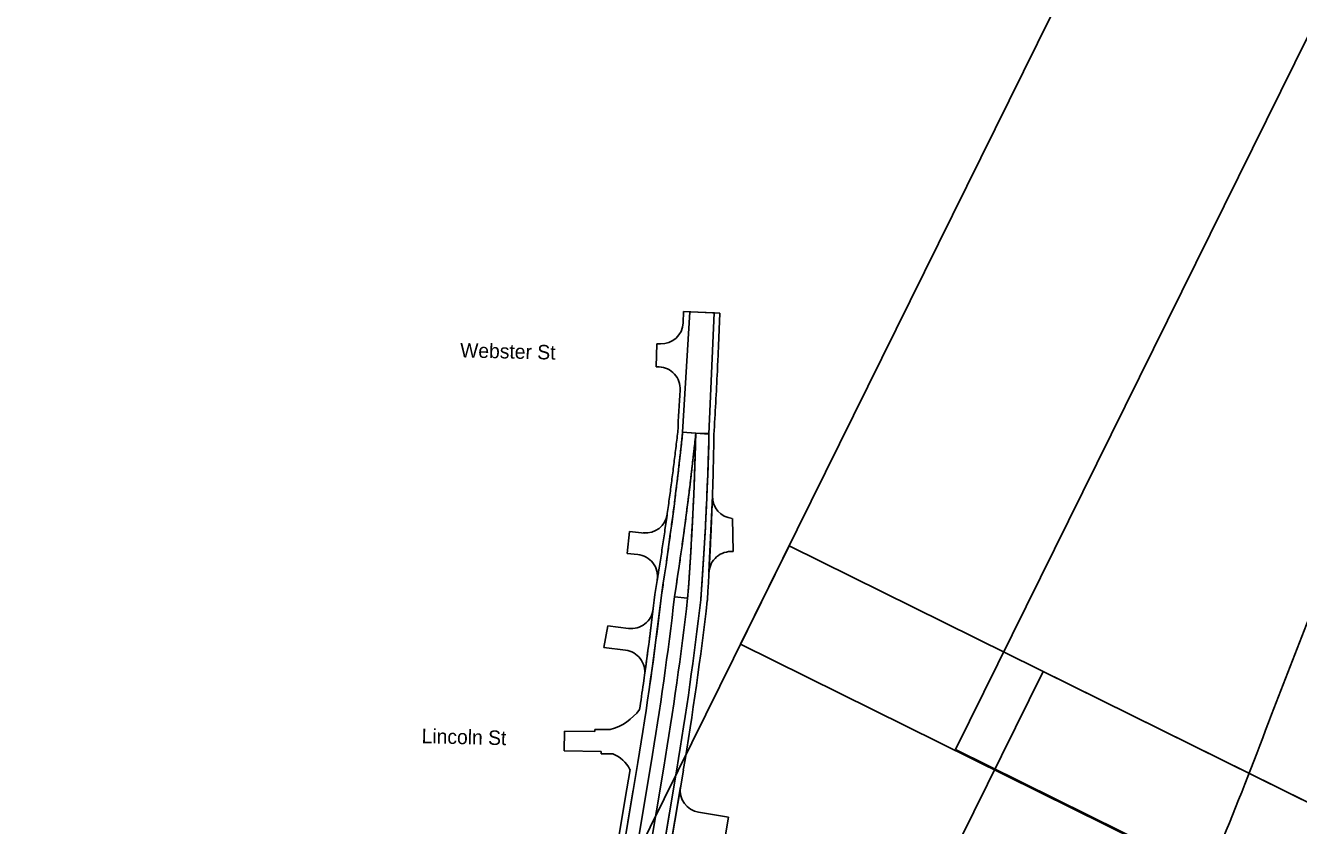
# Model space of a CAD drawing. Extents: x 14097936 to 14128734, y 8632000 to 8683104.
# Drawn here: x 14118632 to 14119790, y 8670096 to 8670823 of the extents above; entities that cross this region are included whole.
import ezdxf

# ---------------------------------------------------------------- set-up
doc = ezdxf.new("R2010")
doc.units = 0
for name, color, linetype in [('dsn_stg_shd_prev', 7, 'Continuous'), ('dsnNonPlotable', 7, 'Continuous'), ('dsnPaintExistingEdgeLineRightWhite', 7, 'Continuous'), ('dsnPaintExistingNoPassingYellow', 7, 'Continuous'), ('dsnPaintPlaceBrokenLaneWhite', 7, 'Continuous'), ('dsnPaintRemoveChannelizingLaneYellow', 7, 'Continuous'), ('dsnShadingPaved', 7, 'Continuous'), ('dsnStdLabel', 7, 'Continuous'), ('dsnStgShadingPropPav', 7, 'Continuous'), ('dsnTextFinalPlan', 7, 'Continuous')]:
    doc.layers.add(name, color=color, linetype=linetype)

msp = doc.modelspace()

# ---------------------------------------------------------------- linework, layer by layer
at = {"layer": 'dsn_stg_shd_prev'}
for p, q in [((14119230.3, 8670563.1), (14119229.9, 8670552.8)), ((14119263.3, 8670561.6), (14119230.3, 8670563.1)), ((14119262, 8670531.8), (14119263.3, 8670561.6)), ((14119206.1, 8670533.7), (14119205.3, 8670512.7)), ((14119209.2, 8670533.6), (14119206.1, 8670533.7)), ((14119261.4, 8670517.3), (14119262, 8670531.8)), ((14119205.3, 8670512.7), (14119207.9, 8670512.7)), ((14119253.4, 8670326.1), (14119256.5, 8670395.6)), ((14119274.7, 8670375), (14119275.3, 8670344.8)), ((14119181, 8670363.1), (14119179, 8670343.2)), ((14119194.6, 8670361.7), (14119181, 8670363.1)), ((14119179, 8670343.2), (14119188.6, 8670342.2)), ((14119161.4, 8670277.5), (14119157.8, 8670257.8)), ((14119180.2, 8670275), (14119161.4, 8670277.5)), ((14119157.8, 8670257.8), (14119177.6, 8670255.2)), ((14119122, 8670181.5), (14119121.8, 8670163.6)), ((14119149.5, 8670181.2), (14119122, 8670181.5)), ((14119149.6, 8670183.2), (14119149.5, 8670181.2)), ((14119163.6, 8670183), (14119149.6, 8670183.2)), ((14119121.8, 8670163.6), (14119155.3, 8670163.1)), ((14119155.3, 8670163.1), (14119155.3, 8670161.1)), ((14119155.3, 8670161.1), (14119166.1, 8670161)), ((14119060.6, 8669134.4), (14119230.1, 8670146.1)), ((14119181.6, 8670146.9), (14119178.6, 8670129.2)), ((14119178.6, 8670129.2), (14119157.4, 8670002.4)), ((14119217.6, 8670071.7), (14119227.6, 8670130.9)), ((14119244, 8670107.9), (14119271.2, 8670103.3)), ((14119271.2, 8670103.3), (14119267.9, 8670083.6))]:
    msp.add_line(p, q, dxfattribs=at)
for centre, radius, start, end in [((14119209.9, 8670553.6), 20, 267.8665, 357.5622), ((14119207.2, 8670492.7), 20, 357.0418, 87.8665), ((14116247.6, 8670645.6), 3016.5, 357.401, 357.5622), ((14116247.6, 8670645.6), 3016.5, 356.3091, 357.401), ((14116247.6, 8670645.6), 2983.5, 356.3091, 357.0418), ((14119276.5, 8670394.9), 20, 178.0946, 264.6093), ((14119195.6, 8670381.7), 20, 264.3037, 351.9832), ((14119186.6, 8670322.3), 20, 350.8222, 84.3037), ((14119273.4, 8670324.9), 20, 84.6093, 176.7725), ((14116247.6, 8670645.6), 2976, 351.8742, 353.4443), ((14119182.8, 8670294.9), 20, 262.604, 353.1855), ((14116247.6, 8670645.6), 2976, 352.0225, 353.1855), ((14116247.6, 8670645.6), 3024, 350.4915, 353.4443), ((14119175, 8670235.4), 20, 352.0225, 82.604), ((14116247.6, 8670645.6), 2976, 351.4136, 351.8742), ((14119150.2, 8670231.2), 50, 285.4983, 323.2854), ((14119154.9, 8670133.1), 30, 27.3614, 68.1986), ((14119247.3, 8670127.6), 20, 170.4915, 260.4915)]:
    msp.add_arc(centre, radius, start, end, dxfattribs=at)
for points in [[(14119225, 8670453.5), (14119224.7, 8670451.1), (14119224.1, 8670446.1), (14119223.2, 8670438.7), (14119222.3, 8670431.3), (14119221.4, 8670423.9), (14119220.5, 8670416.5), (14119219.5, 8670409.1), (14119218.5, 8670401.7), (14119217.5, 8670394.3), (14119216.5, 8670386.9), (14119215.5, 8670379.5), (14119214.4, 8670372.1), (14119213.4, 8670364.8), (14119212.3, 8670357.4), (14119211.2, 8670350), (14119210.1, 8670342.6), (14119208.9, 8670335.3), (14119207.8, 8670327.9), (14119206.6, 8670320.5), (14119205.4, 8670313.2), (14119204.6, 8670308.3), (14119204.2, 8670305.8)], [(14119251.9, 8670300.4), (14119252, 8670302.9), (14119252.4, 8670307.9), (14119252.8, 8670315.5), (14119253.3, 8670323), (14119253.7, 8670330.6), (14119254.1, 8670338.1), (14119254.5, 8670345.7), (14119254.8, 8670353.2), (14119255.2, 8670360.8), (14119255.5, 8670368.3), (14119255.8, 8670375.9), (14119256.1, 8670383.5), (14119256.4, 8670391), (14119256.6, 8670398.6), (14119256.9, 8670406.1), (14119257.1, 8670413.7), (14119257.3, 8670421.2), (14119257.5, 8670428.8), (14119257.6, 8670436.3), (14119257.8, 8670443.9), (14119257.8, 8670448.9), (14119257.9, 8670451.4)], [(14119206.4, 8670319.1), (14119206.4, 8670319.6), (14119206.9, 8670322.5), (14119207.8, 8670327.9), (14119208.9, 8670335.3), (14119210.1, 8670342.6), (14119211.2, 8670350), (14119212.3, 8670357.4), (14119213.4, 8670364.8), (14119214.4, 8670371.9), (14119215.1, 8670376.7), (14119215.4, 8670378.9)]]:
    msp.add_open_spline(points, degree=3, dxfattribs=at)
at = {"layer": 'dsnNonPlotable'}
for points in [[(14119282, 8670260.6), (14119976.8, 8671665.7), (14120882.2, 8671218.1), (14120187.4, 8669813)], [(14119930.2, 8669941), (14120624.9, 8671346.1), (14120172.2, 8671570), (14119477.5, 8670164.8)], [(14118631.6, 8668945.1), (14119326.4, 8670350.2), (14120231.7, 8669902.6), (14119537, 8668497.5)], [(14119315.3, 8668607.1), (14120010, 8670012.2), (14119557.3, 8670236), (14118862.6, 8668830.9)]]:
    msp.add_lwpolyline(points, close=True, dxfattribs=at)
at = {"layer": 'dsnPaintExistingEdgeLineRightWhite'}
msp.add_line((14119184.5, 8670128.2), (14119019.2, 8669141.3), dxfattribs=at)
msp.add_line((14119184.5, 8670128.2), (14119019.2, 8669141.3), dxfattribs=at)
msp.add_lwpolyline([(14119029.9, 8669002.7), (14119054.7, 8669135.4), (14119224.2, 8670147)], dxfattribs=at)
msp.add_lwpolyline([(14119029.9, 8669002.7), (14119054.7, 8669135.4), (14119224.2, 8670147)], dxfattribs=at)
for centre, radius, start, end in [((14116263.1, 8670764.5), 2982.6, 351.1404, 354.0098), ((14116241.7, 8670525.8), 3012.6, 355.7208, 358.5901), ((14116247.6, 8670645.6), 2982, 351.8737, 353.4443), ((14116247.6, 8670645.6), 3018, 350.4915, 353.4443), ((14116594.6, 8671342.6), 3454.2, 336.5576, 340.1043)]:
    msp.add_arc(centre, radius, start, end, dxfattribs=at)
at = {"layer": 'dsnPaintExistingNoPassingYellow'}
for p, q in [((14119031.1, 8669139.3), (14119200.5, 8670151)), ((14119212.3, 8670149), (14119042.9, 8669137.4))]:
    msp.add_line(p, q, dxfattribs=at)
for centre, radius, start, end in [((14116263.1, 8670764.5), 2994.6, 351.1496, 354.019), ((14116241.7, 8670525.8), 3000.6, 355.7299, 358.5992), ((14116247.6, 8670645.6), 2994, 350.4915, 353.4443), ((14116247.6, 8670645.6), 3006, 350.4915, 353.4443)]:
    msp.add_arc(centre, radius, start, end, dxfattribs=at)
at = {"layer": 'dsnPaintPlaceBrokenLaneWhite'}
msp.add_arc((14115416.7, 8671831.7), 4742.6, 334.0912, 339.391, dxfattribs=at)
at = {"layer": 'dsnPaintRemoveChannelizingLaneYellow'}
msp.add_arc((14115570.5, 8671771.3), 4577.4, 336.8089, 339.3131, dxfattribs=at)
at = {"layer": 'dsnShadingPaved'}
for p, q in [((14119241.4, 8670452.5), (14119229.4, 8670453.3)), ((14119253.4, 8670452.2), (14119241.4, 8670452.5)), ((14119234, 8670302.4), (14119222.1, 8670303.8)), ((14119222.1, 8670303.8), (14119234, 8670302.4)), ((14119188.7, 8670153), (14119019.2, 8669141.3)), ((14119200.5, 8670151), (14119031.1, 8669139.3)), ((14119031.1, 8669139.3), (14119200.5, 8670151)), ((14119212.3, 8670149), (14119042.9, 8669137.4)), ((14119042.9, 8669137.4), (14119212.3, 8670149)), ((14119054.7, 8669135.4), (14119224.2, 8670147))]:
    msp.add_line(p, q, dxfattribs=at)
msp.add_lwpolyline([(14119229.4, 8670453.3), (14119235.9, 8670562.8), (14119258.2, 8670561.9), (14119253.4, 8670451.7)], close=True, dxfattribs=at)
for centre, radius, start, end in [((14116247.6, 8670645.6), 2982, 350.4915, 353.4443), ((14116247.6, 8670645.6), 2994, 350.4915, 353.4443), ((14116247.6, 8670645.6), 2994, 350.4915, 353.4443), ((14116247.6, 8670645.6), 3006, 350.4915, 353.4443), ((14116247.6, 8670645.6), 3006, 350.4915, 353.4443), ((14116247.6, 8670645.6), 3018, 350.4915, 353.4443), ((14115570.5, 8671771.3), 4565.4, 336.7987, 339.3131), ((14115570.5, 8671771.3), 4577.4, 336.8089, 339.3131), ((14115570.5, 8671771.3), 4577.4, 336.8089, 339.3131)]:
    msp.add_arc(centre, radius, start, end, dxfattribs=at)
for points in [[(14119229.4, 8670453.3), (14119229.2, 8670450.8), (14119228.7, 8670445.8), (14119227.8, 8670438.4), (14119227, 8670431), (14119226.2, 8670423.5), (14119225.3, 8670416.1), (14119224.4, 8670408.7), (14119223.5, 8670401.3), (14119222.6, 8670393.9), (14119221.7, 8670386.5), (14119220.7, 8670379), (14119219.7, 8670371.6), (14119218.7, 8670364.2), (14119217.7, 8670356.8), (14119216.7, 8670349.4), (14119215.7, 8670342.1), (14119214.6, 8670334.7), (14119213.5, 8670327.3), (14119212.4, 8670319.9), (14119211.3, 8670312.5), (14119210.5, 8670307.6), (14119210.1, 8670305.2)], [(14119222.1, 8670303.8), (14119222.4, 8670306.3), (14119223.2, 8670311.2), (14119224.3, 8670318.6), (14119225.4, 8670326), (14119226.5, 8670333.4), (14119227.6, 8670340.8), (14119228.6, 8670348.3), (14119229.7, 8670355.7), (14119230.7, 8670363.1), (14119231.7, 8670370.5), (14119232.7, 8670378), (14119233.6, 8670385.4), (14119234.6, 8670392.9), (14119235.5, 8670400.3), (14119236.4, 8670407.7), (14119237.3, 8670415.2), (14119238.1, 8670422.6), (14119239, 8670430.1), (14119239.8, 8670437.6), (14119240.6, 8670445), (14119241.2, 8670450), (14119241.4, 8670452.5)], [(14119241.4, 8670452.5), (14119241.2, 8670450), (14119240.6, 8670445), (14119239.8, 8670437.6), (14119239, 8670430.1), (14119238.1, 8670422.6), (14119237.3, 8670415.2), (14119236.4, 8670407.7), (14119235.5, 8670400.3), (14119234.6, 8670392.9), (14119233.6, 8670385.4), (14119232.7, 8670378), (14119231.7, 8670370.5), (14119230.7, 8670363.1), (14119229.7, 8670355.7), (14119228.6, 8670348.3), (14119227.6, 8670340.8), (14119226.5, 8670333.4), (14119225.4, 8670326), (14119224.3, 8670318.6), (14119223.2, 8670311.2), (14119222.4, 8670306.3), (14119222.1, 8670303.8)], [(14119241.4, 8670452.5), (14119241.4, 8670450), (14119241.2, 8670445), (14119241, 8670437.5), (14119240.8, 8670430), (14119240.5, 8670422.5), (14119240.3, 8670415), (14119240, 8670407.5), (14119239.7, 8670400), (14119239.4, 8670392.4), (14119239, 8670384.9), (14119238.6, 8670377.4), (14119238.3, 8670369.9), (14119237.9, 8670362.4), (14119237.4, 8670354.9), (14119237, 8670347.4), (14119236.6, 8670339.9), (14119236.1, 8670332.4), (14119235.6, 8670324.9), (14119235.1, 8670317.4), (14119234.5, 8670309.9), (14119234.2, 8670304.9), (14119234, 8670302.4)], [(14119234, 8670302.4), (14119234.2, 8670304.9), (14119234.5, 8670309.9), (14119235.1, 8670317.4), (14119235.6, 8670324.9), (14119236.1, 8670332.4), (14119236.6, 8670339.9), (14119237, 8670347.4), (14119237.4, 8670354.9), (14119237.9, 8670362.4), (14119238.3, 8670369.9), (14119238.6, 8670377.4), (14119239, 8670384.9), (14119239.4, 8670392.4), (14119239.7, 8670400), (14119240, 8670407.5), (14119240.3, 8670415), (14119240.5, 8670422.5), (14119240.8, 8670430), (14119241, 8670437.5), (14119241.2, 8670445), (14119241.4, 8670450), (14119241.4, 8670452.5)], [(14119246, 8670301.5), (14119246.1, 8670303.1), (14119246.2, 8670304.7), (14119246.4, 8670307), (14119246.4, 8670307.8), (14119246.5, 8670309), (14119246.5, 8670309.4), (14119246.6, 8670310.1), (14119246.7, 8670312.1), (14119246.9, 8670314.1), (14119247, 8670316.4), (14119247.1, 8670317.2), (14119247.2, 8670318.8), (14119247.2, 8670319.5), (14119247.4, 8670321.9), (14119247.5, 8670323.5), (14119247.7, 8670326.6), (14119247.8, 8670328.2), (14119248.1, 8670332.9), (14119248.3, 8670336), (14119249.3, 8670351.7), (14119250, 8670364.3), (14119251.2, 8670389.4), (14119251.8, 8670401.9), (14119252.4, 8670417.6), (14119252.5, 8670420.8), (14119252.6, 8670425.5), (14119252.7, 8670427.1), (14119252.8, 8670430.2), (14119252.8, 8670431.8), (14119252.9, 8670434.1), (14119252.9, 8670434.9), (14119253, 8670436.5), (14119253, 8670437.3), (14119253.1, 8670439.6), (14119253.1, 8670441.2), (14119253.2, 8670443.2), (14119253.2, 8670443.6), (14119253.2, 8670444.3), (14119253.2, 8670444.7), (14119253.3, 8670445.9), (14119253.3, 8670446.7), (14119253.3, 8670449.1), (14119253.4, 8670450.6), (14119253.4, 8670452.2)], [(14119789.1, 8669964), (14119790.9, 8669968.3), (14119796.4, 8669981.2), (14119805.4, 8670002.7), (14119816.1, 8670028.4), (14119826.6, 8670054.3), (14119836.9, 8670080.1), (14119847.1, 8670106.1), (14119857.1, 8670132.1), (14119863.7, 8670149.5), (14119867, 8670158.1)], [(14119789.1, 8669964), (14119790.9, 8669968.3), (14119796.4, 8669981.2), (14119805.4, 8670002.7), (14119816.1, 8670028.4), (14119826.6, 8670054.3), (14119836.9, 8670080.1), (14119847.1, 8670106.1), (14119857.1, 8670132.1), (14119863.7, 8670149.5), (14119867, 8670158.1)]]:
    msp.add_open_spline(points, degree=3, dxfattribs=at)
at = {"layer": 'dsnStdLabel'}
msp.add_line((14119765.1, 8670196.9), (14119798.9, 8670284.1), dxfattribs=at)
msp.add_arc((14115469.5, 8671811), 4588.9, 336.3891, 339.4034, dxfattribs=at)
at = {"layer": 'dsnStgShadingPropPav'}
for p, q in [((14119230.3, 8670563.1), (14119229.9, 8670552.8)), ((14119263.3, 8670561.6), (14119230.3, 8670563.1)), ((14119262, 8670531.8), (14119263.3, 8670561.6)), ((14119206.1, 8670533.7), (14119205.3, 8670512.7)), ((14119209.2, 8670533.6), (14119206.1, 8670533.7)), ((14119261.4, 8670517.3), (14119262, 8670531.8)), ((14119205.3, 8670512.7), (14119207.9, 8670512.7)), ((14119122, 8670181.5), (14119121.8, 8670163.6)), ((14119149.5, 8670181.2), (14119122, 8670181.5)), ((14119149.6, 8670183.2), (14119149.5, 8670181.2)), ((14119163.6, 8670183), (14119149.6, 8670183.2)), ((14119121.8, 8670163.6), (14119155.3, 8670163.1)), ((14119155.3, 8670163.1), (14119155.3, 8670161.1)), ((14119155.3, 8670161.1), (14119166.1, 8670161)), ((14119060.6, 8669134.4), (14119230.1, 8670146.1)), ((14119181.6, 8670146.9), (14119178.6, 8670129.2)), ((14119178.6, 8670129.2), (14119157.4, 8670002.4))]:
    msp.add_line(p, q, dxfattribs=at)
for centre, radius, start, end in [((14119209.9, 8670553.6), 20, 267.8665, 357.5622), ((14119207.2, 8670492.7), 20, 357.0418, 87.8665), ((14116247.6, 8670645.6), 3016.5, 357.401, 357.5622), ((14116247.6, 8670645.6), 3016.5, 356.3091, 357.401), ((14116247.6, 8670645.6), 2983.5, 356.3091, 357.0418), ((14116247.6, 8670645.6), 2976, 351.8742, 353.4443), ((14116247.6, 8670645.6), 3024, 350.4915, 353.4443), ((14116247.6, 8670645.6), 2976, 351.4136, 351.8742), ((14119150.2, 8670231.2), 50, 285.4983, 323.2854), ((14119154.9, 8670133.1), 30, 27.3614, 68.1986)]:
    msp.add_arc(centre, radius, start, end, dxfattribs=at)
for points in [[(14119225, 8670453.5), (14119224.7, 8670451.1), (14119224.1, 8670446.1), (14119223.2, 8670438.7), (14119222.3, 8670431.3), (14119221.4, 8670423.9), (14119220.5, 8670416.5), (14119219.5, 8670409.1), (14119218.5, 8670401.7), (14119217.5, 8670394.3), (14119216.5, 8670386.9), (14119215.5, 8670379.5), (14119214.4, 8670372.1), (14119213.4, 8670364.8), (14119212.3, 8670357.4), (14119211.2, 8670350), (14119210.1, 8670342.6), (14119208.9, 8670335.3), (14119207.8, 8670327.9), (14119206.6, 8670320.5), (14119205.4, 8670313.2), (14119204.6, 8670308.3), (14119204.2, 8670305.8)], [(14119251.9, 8670300.4), (14119252, 8670302.9), (14119252.4, 8670307.9), (14119252.8, 8670315.5), (14119253.3, 8670323), (14119253.7, 8670330.6), (14119254.1, 8670338.1), (14119254.5, 8670345.7), (14119254.8, 8670353.2), (14119255.2, 8670360.8), (14119255.5, 8670368.3), (14119255.8, 8670375.9), (14119256.1, 8670383.5), (14119256.4, 8670391), (14119256.6, 8670398.6), (14119256.9, 8670406.1), (14119257.1, 8670413.7), (14119257.3, 8670421.2), (14119257.5, 8670428.8), (14119257.6, 8670436.3), (14119257.8, 8670443.9), (14119257.8, 8670448.9), (14119257.9, 8670451.4)]]:
    msp.add_open_spline(points, degree=3, dxfattribs=at)

# ---------------------------------------------------------------- texts
at = {"layer": 'dsnTextFinalPlan'}
for s, p in [('Webster St', (14119026.9, 8670521.4)), ('Lincoln St', (14118991.9, 8670170.7))]:
    msp.add_text(s, height=13.12, rotation=358.6374, dxfattribs=at).set_placement(p)

doc.saveas('drawing.dxf')
